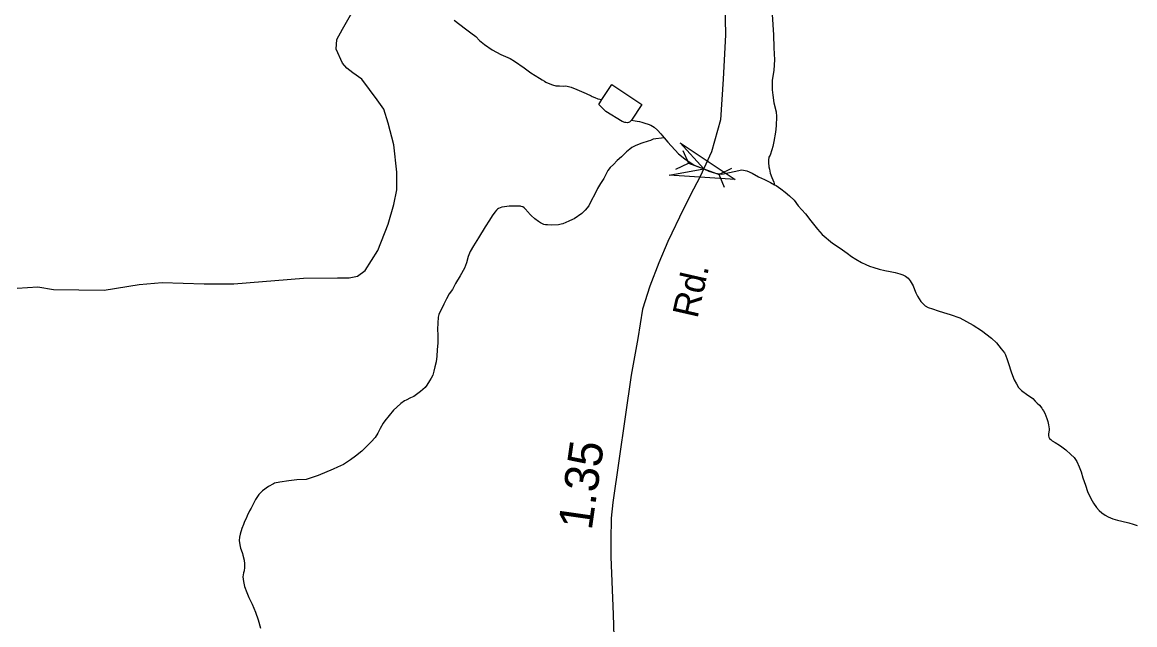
# Model space of a CAD drawing. Extents: x 2220236 to 2384410, y 720751 to 894131.
# Drawn here: x 2318475 to 2322567, y 869383 to 871598 of the extents above; entities that cross this region are included whole.
import ezdxf

# ---------------------------------------------------------------- set-up
doc = ezdxf.new("R2010")
doc.units = 0
doc.layers.add('Default', color=7, linetype='Continuous')

msp = doc.modelspace()

# ---------------------------------------------------------------- linework, layer by layer
at = {"layer": 'Default'}
for p, q in [((2320905.3, 871127.1), (2320925.2, 871080.4)), ((2320879.6, 871058), (2320925.2, 871080.4)), ((2320925.2, 871080.4), (2321038.5, 871038.2)), ((2321084.1, 871060.5), (2321038.5, 871038.2)), ((2321058.4, 870991.4), (2321038.5, 871038.2))]:
    msp.add_line(p, q, dxfattribs=at)
for points in [[(2321060.5, 872335.9), (2321050.2, 872080.2), (2321062.2, 871552.1), (2321052.8, 871389), (2321042.8, 871239.2), (2321010.3, 871121.5), (2320968.2, 871031.8), (2320943.6, 870984.4), (2320906.7, 870912.3), (2320849.6, 870792.8), (2320816.2, 870713.7), (2320782.9, 870627.6), (2320756.5, 870543.2), (2320739, 870436), (2320714.4, 870300.6), (2320647.6, 869833.1), (2320640.6, 869775.1), (2320639.7, 869694.3), (2320639.7, 869632.7), (2320648.5, 869420.1), (2320653.8, 869258.4)], [(2318456.3, 870620.5), (2318531.9, 870625.8), (2318589.8, 870615.3), (2318776, 870613.5), (2318905.1, 870634.6), (2318989.5, 870641.6), (2319144, 870636.4), (2319252.9, 870636.4), (2319509.4, 870657.4), (2319634.1, 870659.2), (2319678, 870659.2), (2319707.9, 870664.5), (2319736.9, 870685.6), (2319782.5, 870759.4), (2319821.2, 870856.1), (2319842.2, 870928.1), (2319852.8, 870982.6), (2319852.8, 871047.6), (2319842.2, 871147.8), (2319821.2, 871226.9), (2319804.4, 871279.5), (2319780.1, 871313.4), (2319751.7, 871351.1), (2319724.6, 871388.6), (2319690.9, 871412.3), (2319668.8, 871430), (2319652.7, 871448), (2319629.7, 871499.4), (2319631.5, 871534.5), (2319652.5, 871573.2), (2319726.3, 871703.2)], [(2321233.6, 871627.5), (2321237.7, 871552.3), (2321239.7, 871503.9), (2321241.7, 871459.8), (2321239.7, 871421.9), (2321233.6, 871383.8), (2321233.6, 871350.2), (2321235.6, 871329.9), (2321239.6, 871302.1), (2321247.7, 871269.6), (2321249.7, 871251.6), (2321247.6, 871217.9), (2321245.6, 871194.1), (2321239.6, 871160.2), (2321235.6, 871141.8), (2321231.7, 871129.5), (2321225.7, 871109.4), (2321221.6, 871102), (2321219.6, 871091.9), (2321220, 871082.2), (2321221.6, 871066.6), (2321223.6, 871058.5), (2321226.4, 871043), (2321231.6, 871027.6), (2321239.6, 871009.9), (2321242.5, 871001)], [(2320063.3, 871605.7), (2320105.4, 871573.9), (2320125.4, 871560.1), (2320143.3, 871546), (2320157.3, 871531.8), (2320175.4, 871516.1), (2320203.4, 871497.4), (2320235.3, 871479.9), (2320269.5, 871465.7), (2320285.5, 871455.8), (2320321.4, 871430.3), (2320345.3, 871412.2), (2320377.3, 871392.3), (2320387.2, 871386.9), (2320395.4, 871381.5), (2320401.4, 871377.7), (2320415.4, 871371.7), (2320425.4, 871367.9), (2320437.9, 871365.2), (2320451.5, 871364.2), (2320465.3, 871363.9), (2320473.3, 871364.3), (2320479.4, 871363.7), (2320493.5, 871360.1), (2320515.5, 871351.2), (2320549.5, 871336.2), (2320567.5, 871327.9), (2320571.6, 871325.5), (2320580.7, 871321.8), (2320592.5, 871317.3), (2320607.3, 871313.9)], [(2320607.3, 871313.9), (2320643.6, 871369.4), (2320753.4, 871296.1), (2320716, 871238.8)], [(2320716, 871238.8), (2320715.4, 871237.9), (2320711.6, 871233.6), (2320709.1, 871231.1), (2320705.5, 871230.1), (2320701.4, 871229.2), (2320695.5, 871229.7), (2320691.1, 871230.3), (2320681.6, 871234.1), (2320621.5, 871270.1), (2320595.4, 871296.2), (2320607.3, 871313.9)], [(2320716, 871238.8), (2320729.5, 871236.1), (2320737.4, 871234.6), (2320744.8, 871233.3), (2320753.9, 871230.5), (2320765.5, 871227.6), (2320777.4, 871224.1), (2320787.6, 871219.5), (2320799.9, 871212.6), (2320811.5, 871201.7), (2320823.5, 871188.1), (2320836.3, 871173.1)], [(2320836.3, 871173.1), (2320795.5, 871168.2), (2320785.5, 871163.6), (2320777.6, 871161.7), (2320753.5, 871154.1), (2320731.4, 871145.8), (2320717.5, 871138), (2320709.6, 871131.9), (2320697.6, 871121.6), (2320679.5, 871103.4), (2320663.5, 871089.7), (2320649.4, 871076), (2320637.5, 871064.1), (2320629.5, 871053.9), (2320613.6, 871023.7), (2320601.5, 871006), (2320591.4, 870987.5), (2320579.4, 870964), (2320569.4, 870943.8), (2320559.4, 870923.8), (2320545.5, 870907.6), (2320533.4, 870895.7), (2320505.4, 870875.6), (2320499.3, 870873.7), (2320485.3, 870867.3), (2320463.3, 870857.4), (2320457.4, 870855.6), (2320447.3, 870853.6), (2320423.3, 870851.8), (2320407.4, 870853.6), (2320399.4, 870854), (2320393.4, 870855.4), (2320381.3, 870861.5), (2320373.3, 870866.2), (2320360.5, 870875.4), (2320347.4, 870888.1), (2320331.3, 870905.4), (2320329.4, 870907.8), (2320325.2, 870911.8), (2320321.3, 870915.6), (2320316.3, 870919.6), (2320309.8, 870921), (2320307.4, 870921.7), (2320293.2, 870921.9), (2320282.8, 870922.3), (2320265.4, 870921.6), (2320249.3, 870920.1), (2320239.3, 870918.1), (2320233.2, 870916.2), (2320226.5, 870914.2), (2320223.2, 870911.6), (2320219, 870907.4), (2320212.8, 870900.6), (2320203.2, 870887), (2320193.4, 870871), (2320177.3, 870845.7), (2320153.3, 870805.3), (2320135.3, 870776), (2320123.1, 870755.7), (2320115.3, 870737.3), (2320109.3, 870713.3), (2320101.3, 870694.1), (2320085.2, 870665.7), (2320069.2, 870637.8), (2320057.2, 870616.1), (2320045.1, 870600), (2320035.3, 870581.4), (2320025.1, 870561.4), (2320017.2, 870543.8), (2320011.1, 870532), (2320007.2, 870523.6), (2320005.2, 870513.7), (2320003, 870469.4), (2320003.1, 870448), (2320003.1, 870419.4), (2320001.1, 870393.9), (2319999.5, 870370.8), (2319997.2, 870349.3), (2319993.1, 870332), (2319989.1, 870315.4), (2319985.1, 870301.2), (2319979, 870289.6), (2319973, 870279.5), (2319963.1, 870263.5), (2319957.2, 870255.9), (2319939.6, 870240.3), (2319925, 870229.9), (2319914.9, 870222.9), (2319903.1, 870217.4), (2319887, 870209.4), (2319881, 870205.9), (2319867.3, 870197.1), (2319853.1, 870183.4), (2319841, 870171.5), (2319824.3, 870152.8), (2319808.9, 870133.1), (2319802.9, 870123.9)], [(2320836.3, 871173.1), (2320849.5, 871158), (2320888.8, 871114.2), (2320912.6, 871096.3), (2320946, 871072.4), (2320981.9, 871059.3), (2321001, 871050.9), (2321024.8, 871043.8), (2321048.7, 871040.2), (2321121.6, 871055.9), (2321140.8, 871051.9), (2321159.6, 871043.7), (2321182.7, 871029.8), (2321205.5, 871020.1), (2321227.6, 871009.4), (2321242.5, 871001)], [(2321242.5, 871001), (2321247.7, 870998.1), (2321265.6, 870985.6), (2321281.7, 870973.8), (2321297.6, 870959.9), (2321313.7, 870944.1), (2321329.6, 870923.4), (2321355.6, 870894), (2321375.6, 870867.9), (2321399.7, 870837.6), (2321417.7, 870818), (2321455.6, 870786.7), (2321483.2, 870767.2), (2321509.6, 870749.5), (2321525.6, 870737.7), (2321541.7, 870727.8), (2321562.4, 870715.4), (2321577.7, 870707.9), (2321591.7, 870701.8), (2321607.6, 870696.1), (2321627.2, 870690.3), (2321647.6, 870685.3), (2321667.6, 870682.1), (2321685.3, 870678.7), (2321702.9, 870673.6), (2321713.7, 870670), (2321723.9, 870664.6), (2321733.6, 870657.6), (2321741.6, 870647.4), (2321751.8, 870629.8), (2321757.1, 870616), (2321761.6, 870603.8), (2321767.7, 870591.8), (2321779.8, 870571.7), (2321789.8, 870561.5), (2321795.8, 870556), (2321807.7, 870550), (2321823.7, 870544.1), (2321843.8, 870537.5), (2321863.6, 870531.7), (2321887.8, 870523.7), (2321923.1, 870511.2), (2321973, 870484.6), (2322003.8, 870465.2), (2322040.6, 870436.3), (2322058.3, 870419.9), (2322075.8, 870397.8), (2322087.8, 870383.5), (2322091.7, 870375.4), (2322097.8, 870358.5), (2322101.7, 870347), (2322113.2, 870309.7), (2322123.7, 870283.9), (2322131.7, 870269.4), (2322139.8, 870255.9), (2322149.9, 870244.7), (2322173.8, 870227.7), (2322183.9, 870221.5), (2322192.2, 870214.5), (2322201.2, 870205), (2322208.7, 870197.9), (2322216.2, 870190), (2322225, 870179.8), (2322228.2, 870174.1), (2322231.8, 870169.5), (2322235.8, 870161.4), (2322240.4, 870151.6), (2322243.8, 870141.2), (2322247.7, 870129.9), (2322249.8, 870117.6), (2322251.1, 870110.2), (2322251.7, 870103.7), (2322251.7, 870099.7), (2322251, 870091.4), (2322249.9, 870085.6), (2322249.4, 870081.6), (2322249.8, 870077.4), (2322251.2, 870072.6), (2322253.8, 870067.7), (2322257.8, 870063.7), (2322263.7, 870059.9), (2322274, 870053), (2322290.2, 870043), (2322298.9, 870037.6), (2322313.7, 870026), (2322331.8, 870009.3), (2322343.7, 869997.6), (2322353.7, 869983.2), (2322362.9, 869964), (2322369.9, 869945.2), (2322375.8, 869923.5), (2322385.5, 869895.9), (2322393.8, 869873.2), (2322405.7, 869847.5), (2322415.8, 869829.9), (2322425.9, 869814.7), (2322435.7, 869803.7)], [(2319802.9, 870123.9), (2319792.1, 870104.6), (2319783, 870087.8), (2319773, 870071.8), (2319758.9, 870055.6), (2319743.9, 870041), (2319724.1, 870021.4), (2319701, 870003.2), (2319682.8, 869989.3), (2319656.1, 869972.6), (2319634.9, 869962.7), (2319619, 869955.5), (2319562.9, 869932), (2319518.9, 869917.7), (2319485.1, 869915.6), (2319455.7, 869912), (2319422.8, 869907.4), (2319402.8, 869903.2), (2319398.9, 869901.4), (2319380.9, 869891.7), (2319358.7, 869875.2), (2319344.9, 869861.4), (2319332.8, 869843.7), (2319322.8, 869823.7), (2319316.7, 869811.8), (2319311.3, 869801.8), (2319302.9, 869783.4), (2319298.9, 869773.5), (2319292.7, 869763.2), (2319288.8, 869751.6), (2319282.8, 869737.4), (2319276.8, 869715.9), (2319274.7, 869705), (2319273.4, 869692.8), (2319274.8, 869677.2), (2319277.8, 869664.2), (2319280.8, 869657.9), (2319284.7, 869645.6), (2319286.8, 869639.1), (2319291.4, 869620.5), (2319292.7, 869607.3), (2319292.9, 869593.5), (2319290.8, 869581.1), (2319288.7, 869573.6), (2319286.9, 869558.7), (2319288.8, 869541.6), (2319292.7, 869523.7), (2319300.9, 869501), (2319308.8, 869483.4), (2319320.8, 869459.2), (2319332.8, 869429.3), (2319342.8, 869401.1), (2319350.8, 869371)], [(2322435.7, 869803.7), (2322445.9, 869794.1), (2322457.9, 869785.6), (2322469.7, 869779.5), (2322487, 869772.8), (2322503.8, 869767.9), (2322519.8, 869763.5), (2322545.9, 869757.2), (2322561, 869753), (2322575.9, 869747.8)]]:
    msp.add_lwpolyline(points, dxfattribs=at)
msp.add_lwpolyline([(2320894.6, 871155.6), (2321097.3, 871020), (2320854, 871036.1), (2320981.9, 871059.3)], close=True, dxfattribs=at)

# ---------------------------------------------------------------- texts
for s, height, rotation, p in [('Rd.', 95, 77.209, (2320958.2, 870506.4)), ('1.35', 125, 81.875, (2320569.4, 869727.8))]:
    msp.add_text(s, height=height, rotation=rotation, dxfattribs=at).set_placement(p)

doc.saveas('drawing.dxf')
